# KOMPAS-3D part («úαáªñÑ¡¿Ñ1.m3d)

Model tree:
1. Ломаная:1
2. Эскиз:1
3. Кинематическая операция:1
     Толщина стенки 1 = 1; Толщина стенки 2 = 0.3
4. Смещенная плоскость:1
     Расстояние = 5.2
5. Зеркальный массив:1  (with: Кинематическая операция:1)  (labels: Экземпляр ( 1 ); Экземпляр ( 2 ))
6. Эскиз:2
7. Операция выдавливания:1
     Расстояние 1 = 5.2; Расстояние 2 = 5.2
8. Смещенная плоскость:2
     Расстояние = 14
9. Эскиз:3
10. Операция выдавливания:2
     Расстояние 1 = 0.4; Расстояние 2 = 0.4
11. Скругление:1
     Радиус = 0.2
12. Эскиз:4
13. Эскиз:5
14. Операция выдавливания:4
     Расстояние 1 = 1.5
15. Эскиз:6
16. Вырезать элемент выдавливания:1
     Расстояние 1 = 10
17. Скругление:2
     Радиус = 0.2

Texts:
  ограждение  фары правое
  stalker61
  Сплав АЛ8  ГОСТ 1583-93
  Экземпляр ( 1 )
  Экземпляр ( 2 )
